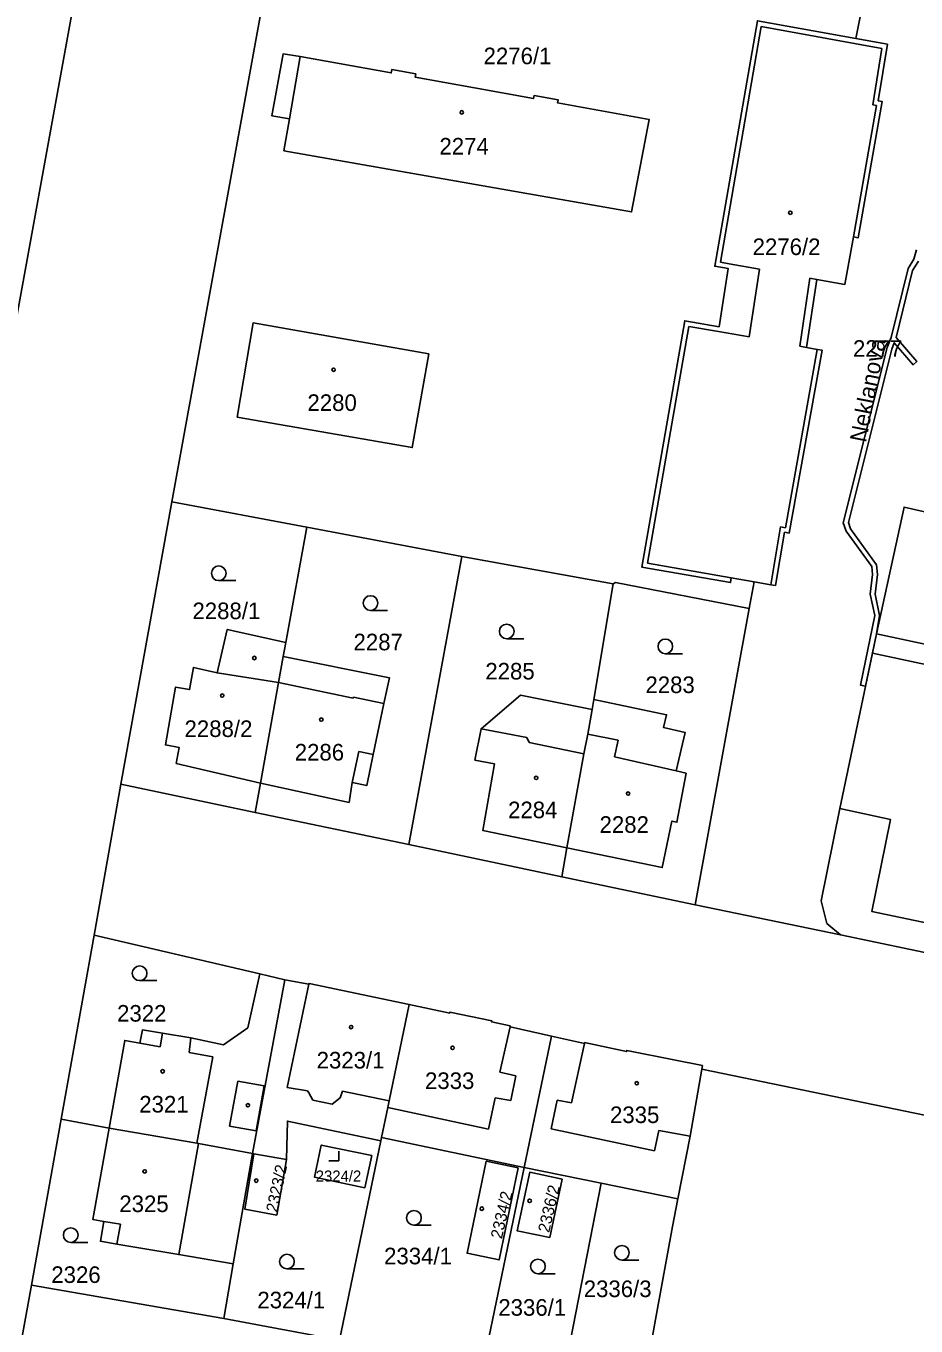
# Model space of a CAD drawing. Extents: x -756746 to -753363, y -1166406 to -1161727.
# Drawn here: x -756092.8 to -756001.6, y -1164670.3 to -1164537.2 of the extents above; entities that cross this region are included whole.
import ezdxf

# ---------------------------------------------------------------- set-up
doc = ezdxf.new("R2010")
doc.units = 0
for name, color, linetype in [('Hranice parcel', 7, 'Continuous'), ('Parcelní čísla', 7, 'Continuous'), ('Pop  PČ popisy', 7, 'Continuous'), ('Vnitřní kresba', 7, 'Continuous'), ('Věcná břemena k části', 7, 'Continuous'), ('Značky budov', 7, 'Continuous'), ('Značky kultur', 7, 'Continuous')]:
    doc.layers.add(name, color=color, linetype=linetype)

msp = doc.modelspace()

# ---------------------------------------------------------------- linework, layer by layer
at = {"layer": 'Hranice parcel'}
for p, q in [((-756007.77, -1164538.46), (-756002.86, -1164513.82)), ((-756094.85, -1164573.11), (-756088.12, -1164536.1)), ((-756077.85, -1164585.92), (-756083.05, -1164614.83)), ((-756064, -1164588.52), (-756077.85, -1164585.92)), ((-756064, -1164588.52), (-756066.18, -1164600.32)), ((-756048.13, -1164591.52), (-756064, -1164588.52)), ((-756053.57, -1164621.04), (-756048.13, -1164591.52)), ((-756048.13, -1164591.52), (-756032.65, -1164594.32)), ((-756018.69, -1164596.84), (-756018.2, -1164594.11)), ((-756032.65, -1164594.32), (-756034.62, -1164606.16)), ((-756024.23, -1164627.21), (-756018.69, -1164596.84)), ((-756066.18, -1164600.32), (-756066.44, -1164601.77)), ((-756034.79, -1164607.18), (-756042.12, -1164605.72)), ((-756034.62, -1164606.16), (-756034.79, -1164607.18)), ((-756083.05, -1164614.83), (-756085.79, -1164630.32)), ((-756083.05, -1164614.83), (-756069.3, -1164617.76)), ((-756068.77, -1164614.75), (-756069.3, -1164617.76)), ((-756069.3, -1164617.76), (-756053.57, -1164621.04)), ((-756037.9, -1164624.32), (-756053.57, -1164621.04)), ((-756037.37, -1164621.37), (-756037.9, -1164624.32)), ((-756037.9, -1164624.32), (-756024.23, -1164627.21)), ((-756009.35, -1164630.29), (-756024.23, -1164627.21)), ((-756085.79, -1164630.32), (-756089.16, -1164649.15)), ((-756068.84, -1164634.29), (-756085.79, -1164630.32)), ((-756009.35, -1164630.29), (-755953.45, -1164641.99)), ((-756069.59, -1164652.69), (-756066.27, -1164634.89)), ((-756066.27, -1164634.89), (-756068.84, -1164634.29)), ((-756041.75, -1164654.12), (-756038.96, -1164640.67)), ((-756024.74, -1164650.91), (-756023.54, -1164644.05)), ((-756023.54, -1164644.05), (-756023.48, -1164643.67)), ((-756023.54, -1164644.05), (-755994.28, -1164650.09)), ((-756089.16, -1164649.15), (-756092.21, -1164666.15)), ((-756089.16, -1164649.15), (-756084.27, -1164650.08)), ((-756060.66, -1164671.79), (-756056.42, -1164651.39)), ((-756056.42, -1164651.39), (-756056.35, -1164651.03)), ((-756056.35, -1164651.03), (-756041.75, -1164654.12)), ((-756026, -1164657.31), (-756024.74, -1164650.91)), ((-756069.59, -1164652.69), (-756071.55, -1164663.98)), ((-756069.59, -1164652.69), (-756069.44, -1164652.72)), ((-756069.44, -1164652.72), (-756066.11, -1164653.3)), ((-756045.99, -1164674.59), (-756041.75, -1164654.12)), ((-756041.75, -1164654.12), (-756033.88, -1164655.72)), ((-756037.89, -1164676.25), (-756033.88, -1164655.72)), ((-756033.88, -1164655.72), (-756026, -1164657.31)), ((-756071.55, -1164663.98), (-756072.53, -1164669.59)), ((-756092.21, -1164666.15), (-756072.53, -1164669.59)), ((-756072.53, -1164669.59), (-756060.66, -1164671.79))]:
    msp.add_line(p, q, dxfattribs=at)
for points in [[(-756057, -1164504.12), (-756060.81, -1164505.08), (-756063.72, -1164508.21), (-756077.85, -1164585.92)], [(-756007.77, -1164538.46), (-756017.86, -1164536.63), (-756022.23, -1164561.78), (-756020.84, -1164562.03), (-756021.78, -1164567.99), (-756025.31, -1164567.37), (-756029.71, -1164592.61), (-756020.63, -1164594.2), (-756020.55, -1164593.7), (-756018.2, -1164594.11)], [(-756018.2, -1164594.11), (-756016.5, -1164594.41), (-756016.01, -1164594.49), (-756015.08, -1164589.04), (-756014.59, -1164589.13), (-756011.24, -1164570.39), (-756011.73, -1164570.3), (-756012.83, -1164570.1), (-756011.78, -1164563.14), (-756008.89, -1164563.65), (-756008.02, -1164558.79), (-756007.54, -1164558.88), (-756005.07, -1164544.92), (-756005.48, -1164544.83), (-756004.55, -1164539.05), (-756007.77, -1164538.46)], [(-756052.84, -1164542.08), (-756055.31, -1164541.64), (-756055.37, -1164541.98), (-756064.69, -1164540.3), (-756066.42, -1164540.02), (-756067.6, -1164546.37), (-756065.79, -1164546.68), (-756066.36, -1164549.95), (-756048.67, -1164553.06), (-756030.74, -1164556.22), (-756028.95, -1164546.75), (-756038.32, -1164545.06), (-756038.26, -1164544.75), (-756040.74, -1164544.3), (-756040.8, -1164544.61), (-756046.84, -1164543.52), (-756052.9, -1164542.43), (-756052.84, -1164542.08)], [(-756071.14, -1164577.25), (-756053.21, -1164580.37), (-756051.53, -1164570.76), (-756069.51, -1164567.6), (-756071.14, -1164577.25)], [(-755999.7, -1164587.18), (-756002.83, -1164586.45), (-756005.66, -1164599.43)], [(-756018.69, -1164596.84), (-756032.39, -1164594.19), (-756032.65, -1164594.32)], [(-756068.77, -1164614.75), (-756077.39, -1164612.72), (-756077.1, -1164611.07), (-756078.5, -1164610.82), (-756077.46, -1164604.89), (-756076.03, -1164605.15), (-756075.63, -1164602.89), (-756073.21, -1164603.45), (-756072.17, -1164598.99), (-756066.18, -1164600.32)], [(-756005.66, -1164599.43), (-756006.07, -1164601.43), (-756009.42, -1164617.35)], [(-755999.09, -1164600.85), (-756005.66, -1164599.43)], [(-756066.44, -1164601.77), (-756066.93, -1164604.42), (-756068.77, -1164614.75)], [(-756068.77, -1164614.75), (-756059.69, -1164616.72), (-756059.36, -1164614.68), (-756057.88, -1164614.99), (-756057.21, -1164611.79), (-756056.11, -1164606.57), (-756055.56, -1164603.95), (-756066.44, -1164601.77)], [(-756042.12, -1164605.72), (-756046.17, -1164609.17), (-756046.79, -1164612.37), (-756044.79, -1164612.76), (-756046, -1164619.58), (-756037.37, -1164621.37)], [(-756037.37, -1164621.37), (-756027.61, -1164623.39), (-756026.62, -1164618.62), (-756026.11, -1164618.74), (-756025.17, -1164613.72), (-756026.17, -1164613.49), (-756025.27, -1164609.55), (-756027.47, -1164609.05), (-756027.17, -1164607.73), (-756034.62, -1164606.16)], [(-756034.79, -1164607.18), (-756035.22, -1164609.73), (-756035.63, -1164611.75), (-756037.37, -1164621.37)], [(-756009.42, -1164617.35), (-756011.34, -1164626.8), (-756010.75, -1164629.11), (-756009.35, -1164630.29)], [(-756009.42, -1164617.35), (-756004.22, -1164618.47), (-756006.13, -1164627.89), (-755974.83, -1164634.45)], [(-756068.84, -1164634.29), (-756070.05, -1164639.8), (-756072.55, -1164641.53), (-756075.89, -1164640.84), (-756078.8, -1164640.36), (-756080.86, -1164640.02), (-756081.12, -1164641.37), (-756082.66, -1164641.09), (-756084.27, -1164650.08)], [(-756053.54, -1164637.41), (-756063.79, -1164635.25), (-756063.81, -1164635.34), (-756066.27, -1164634.89)], [(-756056.35, -1164651.03), (-756055.71, -1164647.97), (-756055.57, -1164647.29), (-756053.54, -1164637.41)], [(-756038.96, -1164640.67), (-756043.18, -1164639.7), (-756043.2, -1164639.6), (-756045.08, -1164639.2), (-756045.06, -1164639.09), (-756049.35, -1164638.19), (-756049.38, -1164638.29), (-756053.54, -1164637.41)], [(-756023.48, -1164643.67), (-756026.43, -1164643.07), (-756031.25, -1164642.11), (-756031.28, -1164642.23), (-756035.56, -1164641.31), (-756035.58, -1164641.4), (-756038.96, -1164640.67)], [(-756084.27, -1164650.08), (-756085.94, -1164659.43), (-756084.81, -1164659.63), (-756085.15, -1164661.66), (-756083.46, -1164661.95), (-756077.13, -1164663.03), (-756071.55, -1164663.98)], [(-756084.27, -1164650.08), (-756075.27, -1164651.62), (-756075.1, -1164651.65), (-756069.59, -1164652.69)], [(-756066.11, -1164653.3), (-756066, -1164649.36), (-756056.42, -1164651.39)], [(-756069.44, -1164652.72), (-756070.38, -1164658.38), (-756067.1, -1164658.98), (-756066.11, -1164653.3)], [(-756058.06, -1164656.19), (-756063.22, -1164655.12), (-756062.54, -1164651.82), (-756057.36, -1164652.89), (-756058.06, -1164656.19)], [(-756042.37, -1164654.13), (-756044.32, -1164663.58), (-756047.6, -1164662.89), (-756045.63, -1164653.45), (-756042.37, -1164654.13)], [(-756039.11, -1164661.28), (-756042.48, -1164660.6), (-756041.18, -1164654.6), (-756037.87, -1164655.3), (-756039.11, -1164661.28)], [(-756026, -1164657.31), (-756026.56, -1164660.17), (-756028.22, -1164669.31), (-756029.78, -1164677.86)], [(-756092.21, -1164666.15), (-756095.29, -1164683.08), (-756087.9, -1164693.56)]]:
    msp.add_lwpolyline(points, dxfattribs=at)
at = {"layer": 'Vnitřní kresba'}
for p, q in [((-756021.65, -1164561.38), (-756017.46, -1164537.21)), ((-756017.46, -1164537.21), (-756005.12, -1164539.47)), ((-756005.12, -1164539.47), (-756006.05, -1164545.25)), ((-756065.79, -1164546.68), (-756064.69, -1164540.3)), ((-756005.65, -1164545.32), (-756008.02, -1164558.79)), ((-756006.05, -1164545.25), (-756005.65, -1164545.32)), ((-756020.76, -1164561.54), (-756021.65, -1164561.38)), ((-756020.76, -1164561.54), (-756017.65, -1164562.1)), ((-756017.65, -1164562.1), (-756018.71, -1164569.03)), ((-756012.48, -1164563.01), (-756013.51, -1164569.97)), ((-756011.78, -1164563.14), (-756012.48, -1164563.01)), ((-756024.9, -1164567.95), (-756029.13, -1164592.2)), ((-756021.86, -1164568.48), (-756024.9, -1164567.95)), ((-756018.71, -1164569.03), (-756021.86, -1164568.48)), ((-756013.51, -1164569.97), (-756012.83, -1164570.1)), ((-756014.98, -1164588.57), (-756011.73, -1164570.3)), ((-756016.5, -1164594.41), (-756015.49, -1164588.47)), ((-756015.49, -1164588.47), (-756014.98, -1164588.57)), ((-756029.13, -1164592.2), (-756020.55, -1164593.7)), ((-756006.07, -1164601.43), (-755999.51, -1164602.82)), ((-756073.21, -1164603.45), (-756066.93, -1164604.42)), ((-756066.93, -1164604.42), (-756059.26, -1164606.02)), ((-756059.26, -1164606.02), (-756059.23, -1164605.92)), ((-756059.23, -1164605.92), (-756056.11, -1164606.57)), ((-756046.17, -1164609.17), (-756041.49, -1164610.07)), ((-756041.49, -1164610.07), (-756041.23, -1164610.58)), ((-756032.11, -1164610.34), (-756035.22, -1164609.73)), ((-756058.69, -1164611.48), (-756059.36, -1164614.68)), ((-756057.21, -1164611.79), (-756058.69, -1164611.48)), ((-756041.23, -1164610.58), (-756035.63, -1164611.75)), ((-756032.5, -1164612.05), (-756032.11, -1164610.34)), ((-756026.17, -1164613.49), (-756032.5, -1164612.05)), ((-756066.02, -1164645.91), (-756063.81, -1164635.34)), ((-756078.8, -1164640.36), (-756079.03, -1164641.75)), ((-756076.07, -1164642.33), (-756075.89, -1164640.84)), ((-756043.18, -1164639.7), (-756044.23, -1164644.35)), ((-756079.03, -1164641.75), (-756081.12, -1164641.37)), ((-756036.9, -1164647.49), (-756035.58, -1164641.4)), ((-756073.64, -1164642.79), (-756076.07, -1164642.33)), ((-756075.27, -1164651.62), (-756073.64, -1164642.79)), ((-756044.23, -1164644.35), (-756042.62, -1164644.72)), ((-756042.62, -1164644.72), (-756043.11, -1164647.25)), ((-756071.09, -1164645.27), (-756071.92, -1164649.88)), ((-756068.37, -1164645.74), (-756071.09, -1164645.27)), ((-756068.37, -1164645.74), (-756069.21, -1164650.37)), ((-756063.94, -1164646.25), (-756066.02, -1164645.91)), ((-756063.82, -1164646.48), (-756063.94, -1164646.25)), ((-756063.41, -1164647.22), (-756063.82, -1164646.48)), ((-756061.42, -1164647.64), (-756063.41, -1164647.22)), ((-756060.6, -1164646.98), (-756061.42, -1164647.64)), ((-756060.36, -1164646.3), (-756060.6, -1164646.98)), ((-756055.57, -1164647.29), (-756060.36, -1164646.3)), ((-756044.72, -1164646.96), (-756045.4, -1164650.19)), ((-756043.11, -1164647.25), (-756044.72, -1164646.96)), ((-756039, -1164650.16), (-756038.36, -1164647.22)), ((-756038.36, -1164647.22), (-756036.9, -1164647.49)), ((-756045.4, -1164650.19), (-756055.71, -1164647.97)), ((-756071.92, -1164649.88), (-756069.21, -1164650.37)), ((-756028.4, -1164652.42), (-756039, -1164650.16)), ((-756027.96, -1164650.31), (-756028.4, -1164652.42)), ((-756024.74, -1164650.91), (-756027.96, -1164650.31)), ((-756077.13, -1164663.03), (-756075.1, -1164651.65)), ((-756083.11, -1164659.92), (-756084.81, -1164659.63)), ((-756083.46, -1164661.95), (-756083.11, -1164659.92))]:
    msp.add_line(p, q, dxfattribs=at)
at = {"layer": 'Věcná břemena k části'}
msp.add_lwpolyline([(-756001.57, -1164560.11), (-756001.83, -1164561.07), (-756002.43, -1164562.03), (-756004.17, -1164569.08), (-756004.57, -1164570.12), (-756009.06, -1164588.06), (-756008.76, -1164588.92), (-756006.15, -1164592.54), (-756006.06, -1164593.38), (-756006.3, -1164595.39), (-756005.84, -1164597.58), (-756007.3, -1164604.69), (-756006.78, -1164604.8), (-756005.66, -1164599.43), (-756005.34, -1164597.56), (-756005.8, -1164595.37), (-756005.56, -1164593.38), (-756005.67, -1164592.36), (-756008.32, -1164588.68), (-756008.54, -1164588.04), (-756004.09, -1164570.28), (-756003.85, -1164569.63), (-756001.91, -1164571.87), (-756001.53, -1164571.55), (-756003.66, -1164569.08), (-756001.97, -1164562.23), (-756001.37, -1164561.27)], dxfattribs=at)
at = {"layer": 'Značky budov'}
for centre in [(-756048.14, -1164546.02), (-756014.49, -1164556.31), (-756061.27, -1164572.39), (-756069.39, -1164601.92), (-756072.68, -1164605.77), (-756062.53, -1164608.23), (-756040.52, -1164614.2), (-756031.11, -1164615.81), (-756059.48, -1164639.73), (-756049.08, -1164641.85), (-756078.78, -1164644.26), (-756030.22, -1164645.48), (-756070.05, -1164647.74), (-756080.62, -1164654.51), (-756069.19, -1164655.46), (-756046.09, -1164658.33), (-756041.19, -1164657.53)]:
    msp.add_circle(centre, 0.175, dxfattribs=at)
at = {"layer": 'Značky kultur'}
for p, q in [((-756073.03, -1164593.99), (-756071.28, -1164593.99)), ((-756057.49, -1164597.04), (-756055.74, -1164597.04)), ((-756043.54, -1164599.95), (-756041.79, -1164599.95)), ((-756027.29, -1164601.48), (-756025.54, -1164601.48)), ((-756081.14, -1164634.97), (-756079.39, -1164634.97)), ((-756060.75, -1164653.43), (-756060.75, -1164652.43)), ((-756061.75, -1164653.43), (-756060.75, -1164653.43)), ((-756053.04, -1164660.02), (-756051.29, -1164660.02)), ((-756088.2, -1164661.79), (-756086.45, -1164661.79)), ((-756066.05, -1164664.5), (-756064.3, -1164664.5)), ((-756031.74, -1164663.6), (-756029.99, -1164663.6)), ((-756040.34, -1164665), (-756038.59, -1164665))]:
    msp.add_line(p, q, dxfattribs=at)
for centre in [(-756073.03, -1164593.24), (-756057.49, -1164596.29), (-756043.54, -1164599.2), (-756027.29, -1164600.73), (-756081.14, -1164634.22), (-756053.04, -1164659.27), (-756088.2, -1164661.04), (-756031.74, -1164662.85), (-756066.05, -1164663.75), (-756040.34, -1164664.25)]:
    msp.add_circle(centre, 0.75, dxfattribs=at)

# ---------------------------------------------------------------- texts
at = {"layer": 'Parcelní čísla'}
for s, height, p in [('2276/1', 1.7, (-756045.91, -1164541.09)), ('2274', 1.7, (-756050.43, -1164550.34)), ('2276/2', 1.7, (-756018.35, -1164560.64)), ('2277', 1.7, (-756008.07, -1164571.06)), ('2280', 1.7, (-756063.95, -1164576.61)), ('2288/1', 1.7, (-756075.73, -1164597.94)), ('2287', 1.7, (-756059.23, -1164601.13)), ('2285', 1.7, (-756045.73, -1164604.12)), ('2283', 1.7, (-756029.33, -1164605.51)), ('2288/2', 1.7, (-756076.54, -1164610.01)), ('2286', 1.7, (-756065.25, -1164612.42)), ('2284', 1.7, (-756043.4, -1164618.33)), ('2282', 1.7, (-756034.03, -1164619.83)), ('2322', 1.7, (-756083.45, -1164639.17)), ('2323/1', 1.7, (-756063.01, -1164643.97)), ('2333', 1.7, (-756051.91, -1164646.07)), ('2321', 1.7, (-756081.18, -1164648.48)), ('2335', 1.7, (-756032.96, -1164649.56)), ('2324/2', 1.139, (-756063.1, -1164655.56)), ('2325', 1.7, (-756083.22, -1164658.68)), ('2334/1', 1.7, (-756056.1, -1164664.03)), ('2326', 1.7, (-756090.19, -1164665.94)), ('2336/3', 1.7, (-756035.65, -1164667.39)), ('2324/1', 1.7, (-756069.08, -1164668.54)), ('2336/1', 1.7, (-756044.4, -1164669.3))]:
    msp.add_text(s, height=height, dxfattribs=at).set_placement(p)
for s, rotation, p in [('2323/2', 78, (-756067.04, -1164658.77)), ('2334/2', 77, (-756044.04, -1164661.49)), ('2336/2', 77, (-756039.19, -1164660.85))]:
    msp.add_text(s, height=1.2, rotation=rotation, dxfattribs=at).set_placement(p)
at = {"layer": 'Pop  PČ popisy'}
msp.add_text('Neklanova', height=1.7, rotation=79, dxfattribs=at).set_placement((-756006.74, -1164579.91))

doc.saveas('drawing.dxf')
